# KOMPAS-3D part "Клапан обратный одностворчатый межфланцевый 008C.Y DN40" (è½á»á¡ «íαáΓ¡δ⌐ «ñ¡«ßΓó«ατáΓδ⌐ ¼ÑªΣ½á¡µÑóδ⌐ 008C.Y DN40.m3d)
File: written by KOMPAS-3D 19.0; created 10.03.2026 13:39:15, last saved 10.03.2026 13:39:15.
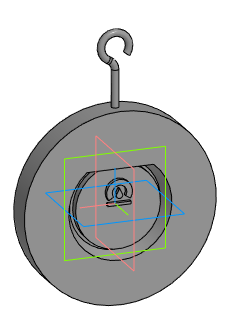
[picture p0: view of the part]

Document properties: Автор: Евгений; Полное имя файла: E:\Dendor\3D для проектировщиков\5.1 Тип 008C. Клапан обратный одностворчатый межфланцевый\stp_Клапан обратный одностворчатый межфланцевый 008C.Y\Клапан обратный одностворчатый межфланцевый 008C.Y DN40.m3d

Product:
- Part/product: Клапан обратный одностворчатый межфланцевый 008C.Y DN40

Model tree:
1. Операция без истории:1  (labels: Клапан обратный одностворчатый межфланцевый 008C.Y DN40)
